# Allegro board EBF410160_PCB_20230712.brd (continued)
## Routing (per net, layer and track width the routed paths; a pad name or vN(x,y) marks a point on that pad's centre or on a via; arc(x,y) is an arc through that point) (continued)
MIPI_CSI_RX_CLK0N: length 108.7
  TOP w0.124: v1(43.21,59.12) 43.06,58.96 43.06,58.63 43.13,58.56 J5.78
  ART03 w0.113: v1(43.21,59.12) 43.04,58.95 43.04,58.53 43.15,58.42 43.8,58.42 44.5,59.12 45.79,59.12 46.48,58.42 46.74,58.42 47.29,58.97 47.29,59.13 46.75,59.67 46.75,60.09 47.1,60.43 47.52,60.43 48.05,59.9 48.21,59.9 50.16,61.85 67.95,61.85 69.28,63.18 78.3,63.18 78.99,62.48 84.84,62.48 85.6,63.24 87.76,63.24 88.58,64.07 92.9,64.07 94.11,65.28 124.79,65.28 126.49,66.98 126.49,68.07 127.51,69.09 128.27,69.09 129.2,70.02 arc(129.25,70.14) 129.2,70.27 arc(129.17,70.35) 129.2,70.43 129.36,70.59 arc(129.44,70.62) 129.52,70.59 arc(129.64,70.54) 129.77,70.59 129.84,70.65 arc(129.89,70.78) 129.84,70.91 arc(129.78,71.03) 129.84,71.16 129.9,71.23 arc(130.03,71.28) 130.16,71.23 arc(130.28,71.17) 130.41,71.23 131.25,72.06 132.21,72.06 132.39,71.88 133.54,71.88 133.72,72.06 134.57,72.06 v1(134.75,72.24)
  BOTTOM w0.124: v1(134.75,72.24) 134.58,72.07 131.37,72.07 131.28,72.16 J23.10
MIPI_CSI_RX_CLK0P: length 108.5
  TOP w0.124: v1(42.55,59.12) 42.73,58.94 42.73,58.64 42.63,58.54 J5.76
  ART03 w0.113: v1(42.55,59.12) 42.72,58.95 42.72,58.4 43.02,58.1 43.93,58.1 44.63,58.8 45.65,58.8 46.35,58.1 46.87,58.1 47.6,58.84 47.6,59.26 47.07,59.8 47.07,59.96 47.23,60.12 47.39,60.12 47.92,59.58 48.34,59.58 50.3,61.53 68.08,61.53 69.41,62.86 78.17,62.86 78.86,62.17 84.97,62.17 85.73,62.93 87.89,62.93 88.71,63.75 93.03,63.75 94.24,64.96 124.92,64.96 126.81,66.85 126.81,67.94 127.64,68.77 128.4,68.77 131.38,71.75 132.08,71.75 132.26,71.57 133.67,71.57 133.85,71.75 134.57,71.75 v1(134.75,71.57)
  BOTTOM w0.124: v1(134.75,71.57) 134.58,71.74 131.37,71.74 131.28,71.66 J23.9
MIPI_CSI_RX_CLK1N: length 133.5
  TOP w0.124: v1(44.7,52.83) 44.45,53.08 44.45,59.7 43.95,60.2 43.38,60.2 43.13,60.45 J5.77
  ART03 w0.113: v1(124.09,55.48) 123.98,55.37 123.52,55.37 123.41,55.48 123.41,56.34 123.11,56.64 122.62,56.64 122.32,56.34 122.32,55.1 122.21,54.99 121.92,54.99 121.81,55.1 121.81,56.34 121.51,56.64 121.02,56.64 120.73,56.34 120.73,55.1 120.61,54.99 120.39,54.99 120.27,55.1 120.27,56.34 119.98,56.64 119.49,56.64 119.19,56.34 119.19,55.12 119.06,54.99 118.82,54.99 118.71,55.1 118.71,55.71 118.41,56.01 117.92,56.01 117.62,55.71 117.62,55.1 117.51,54.99 112.58,54.99 107.06,49.46 103.63,49.46 102.93,48.77 78.74,48.77 76.96,50.54 76.34,50.54 76.05,50.25 76.05,48.81 75.93,48.7 75.71,48.7 75.6,48.81 75.6,50.25 75.3,50.54 74.81,50.54 74.51,50.25 74.51,48.81 74.4,48.7 74.17,48.7 74.06,48.81 74.06,50.25 73.76,50.54 73.26,50.54 72.96,50.25 72.96,49.07 72.85,48.96 72.63,48.96 72.51,49.07 72.51,50.25 72.21,50.54 66.04,50.54 64.77,49.27 59.2,49.27 59.08,49.39 59.08,50.88 58.79,51.18 58.3,51.18 58,50.88 58,49.18 57.72,48.89 57.02,48.89 56.27,49.65 56.27,49.81 57.38,50.91 57.38,51.33 57.03,51.68 56.61,51.68 55.51,50.57 55.35,50.57 55.19,50.73 55.19,50.89 56.21,51.92 56.21,52.34 55.87,52.68 55.45,52.68 54.42,51.66 54.26,51.66 53.72,52.2 50.54,52.2 arc(50.45,52.23) 50.41,52.32 arc(50.38,52.41) 50.29,52.45 50.09,52.45 arc(50,52.41) 49.96,52.32 arc(49.92,52.23) 49.84,52.2 49.64,52.2 arc(49.55,52.23) 49.51,52.32 arc(49.47,52.41) 49.38,52.45 49.19,52.45 arc(49.1,52.41) 49.06,52.32 arc(49.02,52.23) 48.93,52.2 48.36,52.2 48.25,52.31 48.25,52.79 47.95,53.08 47.46,53.08 47.16,52.79 47.16,52.5 47.05,52.38 46.82,52.38 46.71,52.5 46.71,52.79 46.41,53.08 45.93,53.08 45.63,52.79 45.63,52.31 45.52,52.2 44.7,52.2 44.51,52.38 44.51,52.64 v1(44.7,52.83)
  BOTTOM w0.124: J24.10 129.6,55.39 129.5,55.29 124.29,55.29 v1(124.09,55.48)
MIPI_CSI_RX_CLK1P: length 133.6
  TOP w0.124: J5.75 42.63,60.49 43.25,59.87 43.82,59.87 44.12,59.57 44.12,53.01 v1(43.94,52.83)
  ART03 w0.113: v1(43.94,52.83) 44.2,52.58 44.2,52.25 44.57,51.88 45.65,51.88 45.94,52.18 45.94,52.66 46.06,52.77 46.28,52.77 46.4,52.66 46.4,52.37 46.69,52.07 47.18,52.07 47.48,52.37 47.48,52.66 47.59,52.77 47.82,52.77 47.93,52.66 47.93,52.18 48.23,51.88 53.59,51.88 54.13,51.34 54.55,51.34 55.58,52.37 55.74,52.37 55.9,52.21 55.9,52.05 54.87,51.02 54.87,50.6 55.21,50.26 55.64,50.26 56.74,51.36 56.9,51.36 57.06,51.2 57.06,51.04 55.96,49.94 55.96,49.52 56.89,48.58 57.85,48.58 58.32,49.04 58.32,50.75 58.43,50.86 58.65,50.86 58.77,50.75 58.77,49.26 59.07,48.96 64.9,48.96 66.17,50.23 72.08,50.23 72.2,50.12 72.2,48.94 72.49,48.64 72.98,48.64 73.28,48.94 73.28,50.12 73.39,50.23 73.63,50.23 73.74,50.12 73.74,48.68 74.04,48.39 74.53,48.39 74.83,48.68 74.83,50.12 74.94,50.23 75.17,50.23 75.28,50.12 75.28,48.68 75.58,48.39 76.06,48.39 76.36,48.68 76.36,50.12 76.47,50.23 76.83,50.23 78.61,48.45 103.06,48.45 103.76,49.15 107.19,49.15 112.71,54.67 117.64,54.67 117.94,54.97 117.94,55.58 118.05,55.69 118.28,55.69 118.39,55.58 118.39,54.97 118.69,54.67 119.19,54.67 119.51,54.99 119.51,56.21 119.62,56.33 119.85,56.33 119.96,56.21 119.96,54.97 120.26,54.67 120.74,54.67 121.04,54.97 121.04,56.21 121.15,56.33 121.38,56.33 121.49,56.21 121.49,54.97 121.79,54.67 122.34,54.67 122.64,54.97 122.64,56.21 122.75,56.33 122.98,56.33 123.09,56.21 123.09,55.35 123.39,55.06 123.86,55.06 v1(124.09,54.82)
  BOTTOM w0.124: v1(124.09,54.82) 124.23,54.96 129.53,54.96 129.6,54.89 J24.9
MIPI_CSI_RX_D0N: length 108.4
  TOP w0.124: v1(41.21,59.12) 41.06,58.96 41.06,58.63 41.13,58.56 J5.70
  ART03 w0.113: v1(41.21,59.12) 40.94,59.39 40.94,59.93 41.41,60.39 42.54,60.39 43.05,59.88 45.22,59.88 45.61,60.27 arc(45.72,60.32) 45.83,60.27 arc(45.91,60.24) 45.99,60.27 46.15,60.43 arc(46.18,60.51) 46.15,60.59 arc(46.1,60.7) 46.15,60.81 46.25,60.91 arc(46.36,60.96) 46.47,60.91 arc(46.55,60.88) 46.63,60.91 46.79,61.07 arc(46.82,61.15) 46.79,61.23 arc(46.74,61.34) 46.79,61.45 46.88,61.55 arc(46.99,61.6) 47.11,61.55 arc(47.18,61.52) 47.26,61.55 47.42,61.71 arc(47.46,61.79) 47.42,61.87 arc(47.38,61.98) 47.42,62.09 47.63,62.29 67.69,62.29 69.03,63.63 78.74,63.63 78.93,63.44 79.4,63.44 arc(79.47,63.41) 79.5,63.34 arc(79.53,63.27) 79.59,63.24 79.85,63.24 arc(79.92,63.27) 79.95,63.34 arc(79.98,63.41) 80.05,63.44 84.29,63.44 84.68,63.82 87.38,63.82 88.65,65.09 92.71,65.09 93.42,65.79 108.77,65.79 109.07,66.09 109.07,66.25 109.18,66.36 109.41,66.36 109.52,66.25 109.52,66.09 109.82,65.79 110.31,65.79 110.6,66.09 110.6,66.25 110.72,66.36 110.94,66.36 111.06,66.25 111.06,66.09 111.35,65.79 112.23,65.79 112.67,66.23 113.3,66.23 113.74,65.79 123.14,65.79 131.19,73.85 131.75,73.85 arc(131.86,73.8) 131.91,73.69 arc(131.96,73.58) 132.07,73.53 132.2,73.53 arc(132.31,73.58) 132.36,73.69 arc(132.41,73.8) 132.52,73.85 133.35,73.85 133.48,73.72 133.48,73.18 133.36,73.06 133.16,73.06 v1(132.98,73.24)
  BOTTOM w0.124: v1(132.98,73.24) 132.82,73.07 131.37,73.07 131.28,73.16 J23.12
MIPI_CSI_RX_D0P: length 108.4
  TOP w0.124: J5.68 40.63,58.54 40.73,58.64 40.73,58.94 v1(40.55,59.12)
  ART03 w0.113: v1(40.55,59.12) 40.63,59.2 40.63,60.06 41.27,60.7 42.67,60.7 43.18,60.2 45.08,60.2 47.5,62.61 67.56,62.61 68.9,63.94 78.87,63.94 79.06,63.75 84.16,63.75 84.55,64.13 87.25,64.13 88.52,65.4 92.58,65.4 93.29,66.11 108.64,66.11 108.75,66.22 108.75,66.38 109.05,66.67 109.54,66.67 109.84,66.38 109.84,66.22 109.95,66.11 110.18,66.11 110.29,66.22 110.29,66.38 110.59,66.67 111.07,66.67 111.37,66.38 111.37,66.22 111.48,66.11 112.1,66.11 112.54,66.55 113.43,66.55 113.87,66.11 123.01,66.11 131.06,74.17 133.48,74.17 133.79,73.85 133.79,73.04 133.5,72.75 133.16,72.75 v1(132.98,72.57)
  BOTTOM w0.124: v1(132.98,72.57) 132.82,72.74 131.37,72.74 131.28,72.66 J23.11
MIPI_CSI_RX_D1N: length 108.6
  TOP w0.124: J5.74 42.13,56.69 42.03,56.6 42.03,56.3 v1(42.21,56.12)
  ART03 w0.113: v1(42.21,56.12) 42.05,56.27 42.05,56.85 42.29,57.09 47.25,57.09 50.87,60.7 68.39,60.7 69.79,62.1 77.66,62.1 79.12,60.64 80.27,60.64 80.9,61.28 82.05,61.28 82.49,60.84 83.26,60.84 83.87,61.45 85.97,61.45 86.55,62.04 88.9,62.04 89.2,62.34 89.2,62.69 89.31,62.8 89.53,62.8 89.65,62.69 89.65,62.34 89.94,62.04 90.43,62.04 90.73,62.34 90.73,62.69 90.84,62.8 91.07,62.8 91.18,62.69 91.18,62.34 91.48,62.04 92.97,62.04 94.62,63.69 116.08,63.69 116.64,64.25 125.91,64.25 131.45,69.79 132.58,69.79 132.78,69.59 133.7,69.59 134.11,70.01 134.11,70.36 v1(134.37,70.61)
  BOTTOM w0.124: J23.8 133.82,71.16 v1(134.37,70.61)
MIPI_CSI_RX_D1P: length 108.4
  TOP w0.124: J5.72 41.63,56.68 41.7,56.61 41.7,56.27 v1(41.55,56.12)
  ART03 w0.113: v1(41.55,56.12) 41.74,56.31 41.74,56.98 42.16,57.4 44.15,57.4 arc(44.24,57.44) 44.27,57.53 arc(44.31,57.62) 44.4,57.66 44.6,57.66 arc(44.69,57.62) 44.72,57.53 arc(44.76,57.44) 44.85,57.4 45.05,57.4 arc(45.14,57.44) 45.17,57.53 arc(45.21,57.62) 45.3,57.66 45.5,57.66 arc(45.59,57.62) 45.63,57.53 arc(45.66,57.44) 45.75,57.4 47.12,57.4 50.73,61.02 68.26,61.02 69.66,62.42 77.79,62.42 79.25,60.96 80.14,60.96 80.77,61.59 82.18,61.59 82.62,61.16 83.13,61.16 83.74,61.77 85.83,61.77 86.42,62.36 88.77,62.36 88.88,62.47 88.88,62.82 89.18,63.12 89.66,63.12 89.96,62.82 89.96,62.47 90.08,62.36 90.3,62.36 90.41,62.47 90.41,62.82 90.71,63.12 91.2,63.12 91.5,62.82 91.5,62.47 91.61,62.36 92.84,62.36 94.49,64.01 115.95,64.01 116.51,64.56 125.78,64.56 131.32,70.1 132.72,70.1 132.91,69.91 133.57,69.91 133.8,70.14 133.8,70.42 v1(133.6,70.61)
  BOTTOM w0.124: J23.7 131.36,70.66 131.53,70.83 133.48,70.83 133.6,70.7 v1(133.6,70.61)
MIPI_CSI_RX_D2N: length 94.9
  TOP w0.124: J5.69 41.13,62.76 41.02,62.86 41.02,64.27 41.4,64.65 41.4,65.25 41.09,65.57 40.73,65.57 v1(40.51,65.78)
  ART03 w0.113: v1(40.51,65.78) 40.64,65.66 40.83,65.66 43.11,67.94 55.5,67.94 56.45,66.99 65.15,66.99 66.94,68.78 85.24,68.78 87.87,71.41 107.7,71.41 108.5,72.21 119.07,72.21 121.92,75.06 123.19,75.06 124.21,76.07 124.84,76.07 124.97,76.2 v1(124.97,76.45)
MIPI_CSI_RX_D2P: length 95.3
  TOP w0.124: J5.67 40.63,62.85 40.69,62.92 40.69,64.41 41.07,64.79 41.07,65.12 40.95,65.24 40.73,65.24 v1(40.51,65.02)
  ART03 w0.113: v1(40.51,65.02) 40.51,65.06 40.73,65.28 40.89,65.28 41.07,65.46 arc(41.16,65.5) 41.25,65.46 arc(41.34,65.42) 41.44,65.46 41.57,65.6 arc(41.61,65.69) 41.57,65.78 arc(41.54,65.87) 41.57,65.96 41.71,66.1 arc(41.8,66.13) 41.89,66.1 arc(41.98,66.06) 42.07,66.1 42.21,66.24 arc(42.25,66.33) 42.21,66.42 arc(42.17,66.51) 42.21,66.6 43.24,67.63 44.57,67.63 arc(44.64,67.6) 44.67,67.53 arc(44.7,67.46) 44.76,67.44 45.02,67.44 arc(45.09,67.46) 45.12,67.53 arc(45.15,67.6) 45.22,67.63 45.48,67.63 arc(45.54,67.6) 45.57,67.53 arc(45.6,67.46) 45.67,67.44 45.93,67.44 arc(45.99,67.46) 46.02,67.53 arc(46.05,67.6) 46.12,67.63 55.37,67.63 56.32,66.67 65.28,66.67 67.07,68.47 85.37,68.47 88,71.09 107.83,71.09 108.63,71.89 119.2,71.89 122.05,74.74 123.32,74.74 124.34,75.76 124.78,75.76 124.97,75.56 v1(124.97,75.44)
MIPI_CSI_RX_D3N: length 95.7
  TOP w0.124: v1(42.29,64.01) 42.06,63.77 42.06,62.92 42.13,62.84 J5.73
  ART03 w0.113: v1(124.97,78.48) 124.97,78.34 125.15,78.17 125.54,78.17 126.11,77.6 126.11,75.44 125.16,74.49 124.21,74.49 120.83,71.11 109.19,71.11 108.4,70.32 88.34,70.32 85.65,67.63 67.44,67.63 65.72,65.91 54.93,65.91 54.43,66.41 44.12,66.41 42.1,64.39 42.1,64.2 v1(42.29,64.01)
MIPI_CSI_RX_D3P: length 95.7
  TOP w0.124: J5.71 41.63,62.82 41.73,62.92 41.73,63.81 v1(41.53,64.01)
  ART03 w0.113: v1(124.97,77.47) 124.97,77.72 125.09,77.85 125.41,77.85 125.8,77.47 125.8,75.57 125.03,74.8 124.08,74.8 120.7,71.43 109.06,71.43 108.27,70.63 88.21,70.63 85.52,67.94 67.31,67.94 65.59,66.23 55.06,66.23 54.56,66.72 43.99,66.72 42.6,65.34 arc(42.48,65.29) 42.35,65.34 arc(42.23,65.39) 42.1,65.34 42.03,65.27 arc(41.98,65.15) 42.03,65.02 arc(42.09,64.9) 42.03,64.77 41.78,64.52 41.78,64.26 v1(41.53,64.01)
MIPI_DSI_TX0_CLKN: length 114.1
  TOP w0.124: v1(133.56,75.83) 133.37,75.64 133.37,75.64 133.27,75.54 130.91,75.54 130.82,75.62 J21.24 ; v1(37.21,64.01) 37.06,63.85 37.06,62.92 37.13,62.84 J5.53
  ART03 w0.113: v1(37.21,64.01) 37.08,63.88 37.08,63.48 37.24,63.32 42.5,63.32 44.93,65.75 53.56,65.75 53.85,65.47 67.12,65.47 68.83,67.18 79.88,67.18 80.55,66.52 82.77,66.52 83.44,67.18 85.93,67.18 88.04,69.29 109.05,69.29 110.29,70.54 122.99,70.54 125.48,73.02 125.48,74.04 128.65,77.21 130.05,77.21 130.54,76.72 130.54,75.23 130.65,75.12 130.88,75.12 130.99,75.23 130.99,76.24 131.29,76.54 131.78,76.54 132.07,76.24 132.07,75.8 132.19,75.68 133.42,75.68 v1(133.56,75.83)
MIPI_DSI_TX0_CLKP: length 115.4
  TOP w0.124: v1(133.56,75.17) 133.52,75.21 130.99,75.21 130.91,75.12 J21.23 ; J5.51 36.63,62.82 36.73,62.92 36.73,63.83 v1(36.55,64.01)
  ART03 w0.113: v1(133.56,75.17) 133.37,75.37 133.02,75.37 arc(132.92,75.33) 132.88,75.23 arc(132.84,75.14) 132.75,75.1 132.57,75.1 arc(132.47,75.14) 132.43,75.23 arc(132.39,75.33) 132.3,75.37 132.06,75.37 131.76,75.66 131.76,76.11 131.65,76.22 131.42,76.22 131.31,76.11 131.31,75.1 131.01,74.8 130.52,74.8 130.22,75.1 130.22,76.59 129.92,76.9 128.78,76.9 128.19,76.31 arc(128.16,76.23) 128.19,76.14 arc(128.23,76.06) 128.19,75.97 128.04,75.82 arc(127.96,75.79) 127.88,75.82 arc(127.79,75.86) 127.71,75.82 127.56,75.67 arc(127.52,75.59) 127.56,75.5 arc(127.59,75.42) 127.56,75.34 127.41,75.19 arc(127.32,75.15) 127.24,75.19 arc(127.15,75.22) 127.07,75.19 125.79,73.91 125.79,72.89 123.12,70.23 110.42,70.23 109.18,68.98 88.17,68.98 86.06,66.87 83.57,66.87 82.9,66.2 80.42,66.2 79.75,66.87 68.96,66.87 67.25,65.15 53.72,65.15 53.43,65.44 45.06,65.44 42.63,63.01 37.11,63.01 36.77,63.35 36.77,63.79 v1(36.55,64.01)
MIPI_DSI_TX0_D0N: length 115
  TOP w0.124: J21.27 130.82,77.12 130.99,76.96 131.51,76.96 v1(131.64,77.09) ; J5.43 34.63,62.84 34.56,62.92 34.56,65.21 36.4,67.05 v1(36.96,67.05)
  ART03 w0.113: v1(36.96,67.05) 36.91,67.1 36.91,67.58 37.08,67.75 arc(37.15,67.78) 37.23,67.75 arc(37.3,67.72) 37.37,67.75 37.55,67.92 arc(37.58,67.99) 37.55,68.07 arc(37.52,68.14) 37.55,68.21 37.72,68.39 arc(37.79,68.42) 37.87,68.39 arc(37.94,68.36) 38.01,68.39 38.19,68.56 arc(38.22,68.63) 38.19,68.71 arc(38.15,68.78) 38.19,68.85 38.36,69.02 arc(38.43,69.05) 38.5,69.02 arc(38.58,68.99) 38.65,69.02 38.82,69.2 arc(38.85,69.27) 38.82,69.34 arc(38.79,69.42) 38.82,69.49 39.01,69.67 55.99,69.67 56.17,69.49 57.53,68.13 63.85,68.13 65.71,69.99 84.01,69.99 87.23,73.21 107,73.21 108.06,74.27 116.61,74.27 117.66,75.33 117.66,75.88 122.3,80.52 130.56,80.52 132.07,79.01 132.07,78.73 arc(132.03,78.63) 131.93,78.58 arc(131.82,78.54) 131.78,78.44 131.78,78.28 arc(131.82,78.17) 131.93,78.13 arc(132.03,78.09) 132.07,77.99 132.07,77.52 v1(131.64,77.09)
MIPI_DSI_TX0_D0P: length 115.3
  TOP w0.124: v1(36.45,67.56) 34.23,65.34 34.23,62.92 34.13,62.82 J5.41 ; v1(132.38,77.1) 131.91,76.62 J21.26
  ART03 w0.113: v1(132.38,77.1) 132.38,79.14 130.69,80.83 122.17,80.83 117.35,76.01 117.35,75.46 116.48,74.59 107.92,74.59 106.87,73.53 87.1,73.53 83.88,70.31 65.58,70.31 63.72,68.45 57.66,68.45 56.49,69.62 56.12,69.99 38.88,69.99 v1(36.45,67.56)
MIPI_DSI_TX0_D1N: length 115.8
  TOP w0.124: v1(127.64,74.17) 127.82,73.98 128.92,73.98 129.06,74.12 J21.21 ; J5.47 35.63,62.79 35.51,62.92 35.51,63.83 v1(35.69,64.01)
  ART03 w0.113: v1(35.69,64.01) 35.49,63.81 35.49,62.72 35.61,62.61 36.45,62.61 36.89,62.17 36.89,61.13 37,61.02 37.23,61.02 37.34,61.13 37.34,61.99 37.83,62.48 42.87,62.48 45.35,64.96 53.27,64.96 53.56,64.68 65.5,64.68 65.96,64.21 67.01,64.21 68.29,65.49 74.57,65.49 75.43,66.35 76.27,66.35 77.13,65.49 77.94,65.49 78.25,65.8 85.68,65.8 88.32,68.45 92.83,68.45 93.13,68.15 93.13,67.88 93.24,67.77 93.47,67.77 93.58,67.88 93.58,68.15 93.88,68.45 94.37,68.45 94.67,68.15 94.67,67.88 94.78,67.77 95,67.77 95.12,67.88 95.12,68.15 95.41,68.45 95.9,68.45 96.2,68.15 96.2,67.88 96.31,67.77 96.54,67.77 96.65,67.88 96.65,68.15 96.95,68.45 97.44,68.45 97.73,68.15 97.73,67.88 97.85,67.77 98.07,67.77 98.19,67.88 98.19,68.15 98.48,68.45 99.88,68.45 100.18,68.15 100.18,67.86 100.29,67.75 100.52,67.75 100.63,67.86 100.63,68.15 100.93,68.45 101.42,68.45 101.71,68.15 101.71,67.86 101.83,67.75 102.05,67.75 102.17,67.86 102.17,68.15 102.46,68.45 102.95,68.45 103.25,68.15 103.25,67.86 103.36,67.75 103.59,67.75 103.7,67.86 103.7,68.15 104,68.45 104.48,68.45 104.78,68.15 104.78,67.86 104.9,67.75 105.12,67.75 105.23,67.86 105.23,68.15 105.53,68.45 106.03,68.45 106.33,68.15 106.33,67.86 106.44,67.75 106.67,67.75 106.78,67.86 106.78,68.15 107.08,68.45 112.21,68.45 113.48,69.72 123.92,69.72 126.62,72.42 126.62,73.62 127.04,74.04 127.5,74.04 v1(127.64,74.17)
MIPI_DSI_TX0_D1P: length 116.3
  TOP w0.124: J5.45 35.13,62.81 35.18,62.86 35.18,63.85 v1(35.03,64.01) ; v1(127.64,73.51) 127.75,73.62 J21.20
  ART03 w0.113: v1(127.64,73.51) 127.42,73.72 127.17,73.72 126.93,73.49 126.93,72.29 124.05,69.4 113.61,69.4 112.34,68.13 107.21,68.13 107.1,68.02 107.1,67.73 106.8,67.44 106.31,67.44 106.02,67.73 106.02,68.02 105.9,68.13 105.66,68.13 105.55,68.02 105.55,67.73 105.25,67.44 104.76,67.44 104.47,67.73 104.47,68.02 104.35,68.13 104.13,68.13 104.02,68.02 104.02,67.73 103.72,67.44 103.23,67.44 102.93,67.73 102.93,68.02 102.82,68.13 102.59,68.13 102.48,68.02 102.48,67.73 102.18,67.44 101.7,67.44 101.4,67.73 101.4,68.02 101.29,68.13 101.06,68.13 100.95,68.02 100.95,67.73 100.65,67.44 100.16,67.44 99.86,67.73 99.86,68.02 99.75,68.13 98.61,68.13 98.5,68.02 98.5,67.75 98.2,67.45 97.72,67.45 97.42,67.75 97.42,68.02 97.31,68.13 97.08,68.13 96.97,68.02 96.97,67.75 96.67,67.45 96.18,67.45 95.88,67.75 95.88,68.02 95.77,68.13 95.55,68.13 95.43,68.02 95.43,67.75 95.14,67.45 94.65,67.45 94.35,67.75 94.35,68.02 94.24,68.13 94.01,68.13 93.9,68.02 93.9,67.75 93.6,67.45 93.11,67.45 92.82,67.75 92.82,68.02 92.7,68.13 88.45,68.13 85.81,65.49 78.38,65.49 78.07,65.18 77,65.18 76.13,66.04 75.56,66.04 74.7,65.18 68.42,65.18 67.14,63.9 65.83,63.9 65.36,64.36 53.43,64.36 53.14,64.65 45.48,64.65 43,62.17 37.96,62.17 37.65,61.86 37.65,61 37.36,60.7 36.87,60.7 36.57,61 36.57,62.04 36.32,62.29 35.48,62.29 35.18,62.59 35.18,63.85 v1(35.03,64.01)
MIPI_DSI_TX0_D2N: length 114.9
  TOP w0.124: J21.18 129.27,72.62 129.09,72.45 128.46,72.45 v1(128.27,72.64) ; v1(38.73,60.07) 38.53,60.27 38.53,60.5 38.63,60.6 J5.59
  ART03 w0.113: v1(128.27,72.64) 128.24,72.64 128.02,72.41 128.02,71.94 124.59,68.52 123.81,68.52 arc(123.69,68.47) 123.65,68.36 arc(123.6,68.24) 123.49,68.2 123.36,68.2 arc(123.24,68.24) 123.2,68.36 arc(123.15,68.47) 123.04,68.52 122.47,68.52 122.36,68.4 122.36,66.97 122.06,66.67 121.58,66.67 121.28,66.97 121.28,68.4 121.17,68.52 120.94,68.52 120.83,68.4 120.83,66.97 120.53,66.67 120.04,66.67 119.74,66.97 119.74,68.4 119.63,68.52 119.41,68.52 119.29,68.4 119.29,66.97 119,66.67 118.51,66.67 118.21,66.97 118.21,68.4 118.1,68.52 115.58,68.52 115.47,68.4 115.47,66.97 115.17,66.67 114.69,66.67 114.39,66.97 114.39,68.4 114.28,68.52 113.92,68.52 112.65,67.25 107.89,67.25 107.25,66.61 92.97,66.61 92.33,65.98 89.62,65.98 89.33,66.27 89.33,67.26 89.21,67.37 88.99,67.37 88.87,67.26 88.87,66.27 88.58,65.98 88.14,65.98 86.84,64.67 78.96,64.67 78.7,64.4 68.79,64.4 67.44,63.06 45.09,63.06 43.31,61.28 41.02,61.28 40.71,60.96 39.9,60.96 39.58,61.28 39.12,61.28 38.61,60.77 38.61,60.2 v1(38.73,60.07)
MIPI_DSI_TX0_D2P: length 115.3
  TOP w0.124: v1(127.51,72.64) 128.03,72.12 J21.17 ; v1(38.07,60.07) 38.08,60.07 38.2,60.19 38.2,60.6 38.13,60.68 J5.57
  ART03 w0.113: v1(127.51,72.64) 127.7,72.45 127.7,72.07 124.46,68.83 122.34,68.83 122.05,68.54 122.05,67.1 121.93,66.99 121.71,66.99 121.59,67.1 121.59,68.54 121.3,68.83 120.81,68.83 120.51,68.54 120.51,67.1 120.4,66.99 120.17,66.99 120.06,67.1 120.06,68.54 119.76,68.83 119.28,68.83 118.98,68.54 118.98,67.1 118.86,66.99 118.64,66.99 118.53,67.1 118.53,68.54 118.23,68.83 115.45,68.83 115.15,68.54 115.15,67.1 115.04,66.99 114.82,66.99 114.7,67.1 114.7,68.54 114.41,68.83 113.79,68.83 112.52,67.56 107.76,67.56 107.12,66.93 92.84,66.93 92.2,66.29 89.75,66.29 89.64,66.41 89.64,67.39 89.34,67.69 88.86,67.69 88.56,67.39 88.56,66.41 88.45,66.29 88.01,66.29 86.71,64.99 78.83,64.99 78.56,64.72 68.66,64.72 67.31,63.37 44.96,63.37 43.18,61.59 40.89,61.59 40.57,61.27 40.03,61.27 39.71,61.59 38.99,61.59 38.29,60.9 38.29,60.28 38.08,60.07 v1(38.07,60.07)
MIPI_DSI_TX0_D3N: length 115.2
  TOP w0.124: v1(128.17,78.7) 128.43,78.45 128.97,78.45 129.14,78.62 J21.30 ; v1(39.75,64.01) 39.52,63.77 39.52,62.97 39.63,62.86 J5.63
  ART03 w0.113: v1(39.75,64.01) 39.55,64.21 39.55,66.41 arc(39.6,66.53) 39.72,66.58 arc(39.82,66.62) 39.86,66.72 39.86,66.88 arc(39.82,66.98) 39.72,67.03 arc(39.6,67.08) 39.55,67.19 39.55,67.31 arc(39.6,67.43) 39.72,67.48 arc(39.82,67.52) 39.86,67.63 39.86,67.78 arc(39.82,67.89) 39.72,67.93 arc(39.6,67.98) 39.55,68.1 39.55,68.48 39.97,68.9 40.48,68.9 40.59,68.79 40.59,68.11 40.89,67.82 41.38,67.82 41.67,68.11 41.67,68.79 41.79,68.9 42.77,68.9 arc(42.83,68.87) 42.86,68.8 arc(42.89,68.73) 42.96,68.71 43.22,68.71 arc(43.29,68.73) 43.31,68.8 arc(43.34,68.87) 43.41,68.9 55.37,68.9 56.88,67.39 64.85,67.39 66.74,69.28 84.96,69.28 87.56,71.88 106.87,71.88 108.34,73.35 119.32,73.35 120.9,74.93 120.9,76.61 120.49,77.02 120.49,77.18 120.65,77.33 120.81,77.33 121.15,76.99 121.57,76.99 121.92,77.34 121.92,77.76 121.58,78.1 121.58,78.26 123.01,79.69 125.4,79.69 arc(125.47,79.66) 125.49,79.6 arc(125.52,79.53) 125.59,79.5 125.85,79.5 arc(125.92,79.53) 125.94,79.6 arc(125.97,79.66) 126.04,79.69 126.3,79.69 arc(126.37,79.66) 126.4,79.6 arc(126.42,79.53) 126.49,79.5 126.75,79.5 arc(126.82,79.53) 126.85,79.6 arc(126.87,79.66) 126.94,79.69 127.2,79.69 arc(127.27,79.66) 127.3,79.6 arc(127.33,79.53) 127.39,79.5 127.65,79.5 arc(127.72,79.53) 127.75,79.6 arc(127.78,79.66) 127.84,79.69 128.1,79.69 arc(128.17,79.66) 128.2,79.6 arc(128.23,79.53) 128.3,79.5 128.56,79.5 arc(128.62,79.53) 128.65,79.6 arc(128.68,79.66) 128.75,79.69 129.46,79.69 130,79.15 130,78.64 129.72,78.36 129.41,78.36 arc(129.34,78.39) 129.31,78.46 arc(129.26,78.58) 129.15,78.62 129.02,78.62 arc(128.91,78.58) 128.86,78.46 arc(128.83,78.39) 128.76,78.36 128.52,78.36 v1(128.17,78.7)
MIPI_DSI_TX0_D3P: length 114.3
  TOP w0.124: v1(39.09,64.01) 39.19,63.91 39.19,62.94 39.13,62.88 J5.61 ; J21.29 128.25,78.12 v1(128.17,78.04)
  ART03 w0.113: v1(128.17,78.04) 129.85,78.04 130.32,78.51 130.32,79.28 129.59,80.01 122.88,80.01 121.26,78.39 121.26,77.97 121.6,77.63 121.6,77.47 121.44,77.31 121.28,77.31 120.94,77.65 120.52,77.65 120.18,77.31 120.18,76.89 120.59,76.47 120.59,75.06 119.19,73.66 108.21,73.66 106.74,72.19 87.43,72.19 84.83,69.59 66.61,69.59 64.72,67.7 57.01,67.7 55.5,69.21 41.66,69.21 41.36,68.92 41.36,68.25 41.25,68.13 41.02,68.13 40.91,68.25 40.91,68.92 40.61,69.21 39.83,69.21 39.23,68.61 39.23,64.15 v1(39.09,64.01)
MIPI_DSI_TX1_CLKN: length 128.1
  TOP w0.124: v1(128.75,53.47) 128.78,53.44 129.9,53.44 J22.24 ; J5.27 30.63,62.59 30.55,62.66 30.55,63.98 v1(30.71,64.14)
  ART03 w0.113: v1(128.75,53.47) 128.57,53.29 128.04,53.29 126.82,52.07 122.43,52.07 122.05,51.69 122.05,51.48 121.94,51.37 121.71,51.37 121.6,51.48 121.6,52.15 121.3,52.45 120.81,52.45 120.51,52.15 120.51,51.48 120.4,51.37 120.18,51.37 120.06,51.48 120.06,52.15 119.76,52.45 119.28,52.45 118.98,52.15 118.98,51.48 118.87,51.37 118.64,51.37 118.53,51.48 118.53,52.15 118.23,52.45 117.7,52.45 117.35,52.1 117.35,51.56 117.22,51.43 113.66,51.43 108.33,46.1 56.07,46.1 52.64,49.53 36.96,49.53 36.07,50.42 arc(36.03,50.52) 36.07,50.61 arc(36.11,50.71) 36.07,50.8 35.94,50.93 arc(35.84,50.97) 35.75,50.93 arc(35.65,50.89) 35.56,50.93 35.43,51.06 arc(35.39,51.15) 35.43,51.25 arc(35.47,51.34) 35.43,51.44 35.3,51.57 arc(35.2,51.61) 35.11,51.57 arc(35.01,51.53) 34.92,51.57 34.42,52.07 31.88,52.07 30.54,53.41 30.54,54.95 30.65,55.06 30.94,55.06 31.24,55.36 31.24,55.85 30.94,56.14 30.65,56.14 30.54,56.26 30.54,56.48 30.65,56.59 31.2,56.59 31.5,56.89 31.5,57.38 31.2,57.68 30.65,57.68 30.54,57.79 30.54,61.42 30.24,61.72 29.89,61.72 29.78,61.83 29.78,62.19 29.89,62.3 30.24,62.3 30.54,62.6 30.54,63.96 v1(30.71,64.14)
MIPI_DSI_TX1_CLKP: length 128.1
  TOP w0.124: v1(30.05,64.14) 30.23,63.96 30.23,62.66 30.13,62.56 J5.25 ; v1(128.75,52.81) 128.75,52.81 129.06,53.11 129.9,53.11 J22.23
  ART03 w0.113: v1(128.75,52.81) 128.59,52.97 128.17,52.97 126.95,51.75 122.56,51.75 122.36,51.56 122.36,51.35 122.07,51.05 121.58,51.05 121.28,51.35 121.28,52.02 121.17,52.13 120.94,52.13 120.83,52.02 120.83,51.35 120.53,51.05 120.04,51.05 119.75,51.35 119.75,52.02 119.63,52.13 119.41,52.13 119.3,52.02 119.3,51.35 119,51.05 118.51,51.05 118.21,51.35 118.21,52.02 118.1,52.13 117.83,52.13 117.66,51.97 117.66,51.43 117.35,51.12 113.8,51.12 108.46,45.78 55.94,45.78 52.51,49.21 36.83,49.21 34.29,51.75 31.75,51.75 30.22,53.28 30.22,55.08 30.52,55.38 30.81,55.38 30.93,55.49 30.93,55.71 30.81,55.83 30.52,55.83 30.22,56.13 30.22,56.61 30.52,56.91 31.07,56.91 31.18,57.02 31.18,57.25 31.07,57.36 30.52,57.36 30.22,57.66 30.22,61.29 30.11,61.4 29.76,61.4 29.46,61.7 29.46,62.32 29.76,62.61 30.11,62.61 30.22,62.73 30.22,63.96 v1(30.05,64.14)
MIPI_DSI_TX1_D0N: length 127.5
  TOP w0.124: J5.17 28.13,60.51 28.06,60.44 28.06,59.44 v1(28.19,59.31) ; v1(133.35,55.12) 133.35,55.06 133.23,54.94 130.91,54.94 130.82,55.03 J22.27
  ART03 w0.113: v1(28.19,59.31) 28.04,59.15 28.04,53.62 31.37,50.29 33.09,50.29 33.4,49.98 arc(33.48,49.95) 33.55,49.98 arc(33.63,50.01) 33.71,49.98 33.87,49.82 arc(33.91,49.74) 33.87,49.66 arc(33.84,49.58) 33.87,49.5 34.03,49.34 arc(34.11,49.31) 34.19,49.34 arc(34.27,49.38) 34.35,49.34 34.51,49.18 arc(34.54,49.1) 34.51,49.02 arc(34.48,48.94) 34.51,48.87 35.5,47.88 52.14,47.88 55.44,44.58 110.11,44.58 114.17,48.64 125.98,48.64 127.89,50.54 131.83,50.54 132.59,51.31 132.59,54.58 132.89,54.88 133.11,54.88 v1(133.35,55.12)
MIPI_DSI_TX1_D0P: length 127.6
  TOP w0.124: v1(27.43,59.31) 27.73,59.61 27.73,60.41 27.63,60.51 J5.15 ; v1(133.35,54.46) 133.2,54.61 130.91,54.61 130.82,54.53 J22.26
  ART03 w0.113: v1(27.43,59.31) 27.72,59.02 27.72,53.49 31.24,49.98 32.95,49.98 35.37,47.56 52,47.56 55.31,44.26 110.24,44.26 114.3,48.32 126.11,48.32 128.02,50.23 131.96,50.23 132.9,51.18 132.9,54.45 133.02,54.56 133.25,54.56 v1(133.35,54.46)
MIPI_DSI_TX1_D1N: length 128.6
  TOP w0.124: v1(29.19,60.07) 29.03,60.22 29.03,60.6 29.13,60.7 J5.21 ; v1(131.95,52.2) 131.7,51.94 130.91,51.94 130.82,52.03 J22.21
  ART03 w0.113: v1(29.19,60.07) 28.99,59.88 28.99,58.61 29.11,58.49 29.42,58.49 29.72,58.2 29.72,57.71 29.42,57.41 28.98,57.41 28.87,57.3 28.87,57.07 28.98,56.96 29.42,56.96 29.72,56.66 29.72,56.18 29.42,55.88 28.98,55.88 28.87,55.76 28.87,55.54 28.98,55.43 29.42,55.43 29.72,55.13 29.72,54.64 29.42,54.34 28.98,54.34 28.87,54.23 28.87,53.94 31.62,51.18 33.72,51.18 34.18,50.72 arc(34.26,50.68) 34.34,50.72 arc(34.42,50.75) 34.5,50.72 34.66,50.56 arc(34.69,50.48) 34.66,50.4 arc(34.63,50.32) 34.66,50.24 34.82,50.08 arc(34.9,50.05) 34.98,50.08 arc(35.06,50.11) 35.14,50.08 35.3,49.92 arc(35.33,49.84) 35.3,49.76 arc(35.27,49.68) 35.3,49.6 36.13,48.77 52.32,48.77 55.75,45.34 108.97,45.34 114.06,50.43 119.72,50.43 120.02,50.14 120.02,49.7 120.14,49.59 120.36,49.59 120.47,49.7 120.47,50.14 120.77,50.43 121.26,50.43 121.56,50.14 121.56,49.7 121.67,49.59 121.9,49.59 122.01,49.7 122.01,50.14 122.31,50.43 122.79,50.43 123.09,50.14 123.09,49.7 123.2,49.59 123.43,49.59 123.54,49.7 123.54,50.14 123.84,50.43 124.33,50.43 124.63,50.14 124.63,49.7 124.74,49.59 124.96,49.59 125.08,49.7 125.08,50.14 125.74,50.8 126.87,50.8 127.53,51.46 129.06,51.46 129.86,52.26 130.81,52.26 131.07,52 131.76,52 v1(131.95,52.2)
MIPI_DSI_TX1_D1P: length 128.5
  TOP w0.124: v1(131.95,51.43) 131.78,51.61 130.91,51.61 130.82,51.53 J22.20 ; J5.19 28.63,60.68 28.71,60.6 28.71,60.25 v1(28.53,60.07)
  ART03 w0.113: v1(131.95,51.43) 131.7,51.69 130.94,51.69 130.68,51.94 129.99,51.94 129.19,51.14 127.66,51.14 127,50.48 125.87,50.48 125.39,50.01 125.39,49.57 125.09,49.27 124.61,49.27 124.31,49.57 124.31,50.01 124.2,50.12 123.97,50.12 123.86,50.01 123.86,49.57 123.56,49.27 123.07,49.27 122.78,49.57 122.78,50.01 122.66,50.12 122.44,50.12 122.32,50.01 122.32,49.57 122.03,49.27 121.54,49.27 121.24,49.57 121.24,50.01 121.13,50.12 120.9,50.12 120.79,50.01 120.79,49.57 120.49,49.27 120,49.27 119.71,49.57 119.71,50.01 119.59,50.12 114.19,50.12 109.1,45.02 55.62,45.02 52.19,48.45 36,48.45 33.59,50.86 31.49,50.86 28.55,53.81 28.55,54.36 28.85,54.66 29.29,54.66 29.4,54.77 29.4,55 29.29,55.11 28.85,55.11 28.55,55.41 28.55,55.9 28.85,56.19 29.29,56.19 29.4,56.31 29.4,56.53 29.29,56.64 28.85,56.64 28.55,56.94 28.55,57.43 28.85,57.73 29.29,57.73 29.4,57.84 29.4,58.07 29.29,58.18 28.97,58.18 28.68,58.48 28.68,59.92 v1(28.53,60.07)
MIPI_DSI_TX1_D2N: length 128.2
  TOP w0.124: J5.33 32.13,62.84 32.06,62.92 32.06,63.17 v1(32.21,63.32) ; J22.18 129.27,50.53 129.23,50.49 128.96,50.49 127.71,51.74 127.71,52.73 127.1,53.33 126.5,53.33 v1(126.36,53.47)
  ART03 w0.113: v1(126.36,53.47) 126.36,53.45 126.23,53.32 117.2,53.32 116.2,52.32 113.03,52.32 107.7,46.99 72.14,46.99 70.42,48.7 69.88,48.7 69.58,48.4 69.58,47.42 69.47,47.3 69.24,47.3 69.13,47.42 69.13,48.4 68.83,48.7 67.12,48.7 65.53,47.12 56.2,47.12 52.77,50.54 37.66,50.54 37.37,50.83 arc(37.34,50.91) 37.37,50.99 arc(37.41,51.06) 37.37,51.14 37.21,51.3 arc(37.13,51.34) 37.06,51.3 arc(36.98,51.27) 36.9,51.3 36.74,51.47 arc(36.7,51.54) 36.74,51.62 arc(36.77,51.7) 36.74,51.78 36.58,51.94 arc(36.5,51.98) 36.42,51.94 arc(36.34,51.91) 36.26,51.94 36.1,52.1 arc(36.07,52.18) 36.1,52.26 arc(36.13,52.34) 36.1,52.42 35.94,52.58 arc(35.86,52.61) 35.78,52.58 arc(35.7,52.55) 35.62,52.58 35.24,52.96 32.62,52.96 32.51,53.07 32.51,53.5 32.62,53.61 33.99,53.61 34.29,53.91 34.29,54.4 33.99,54.69 32.62,54.69 32.51,54.81 32.51,55.24 32.64,55.37 33.23,55.37 33.52,55.67 33.52,56.52 31.5,58.55 31.5,60.68 31.61,60.79 32.6,60.79 32.89,61.09 32.89,61.58 32.6,61.88 31.61,61.88 31.5,61.99 31.5,62.23 32,62.74 32,63.12 v1(32.21,63.32)
MIPI_DSI_TX1_D2P: length 128.1
  TOP w0.124: J22.17 129.16,50.02 129.03,50.16 128.83,50.16 127.38,51.61 127.38,52.59 126.97,53.01 126.57,53.01 v1(126.36,52.81) ; v1(31.55,63.32) 31.73,63.14 31.73,62.92 31.63,62.82 J5.31
  ART03 w0.113: v1(31.55,63.32) 31.69,63.18 31.69,62.87 31.18,62.36 31.18,61.86 31.48,61.56 32.46,61.56 32.58,61.45 32.58,61.22 32.46,61.11 31.48,61.11 31.18,60.81 31.18,58.42 33.21,56.39 33.21,55.8 33.1,55.69 32.51,55.69 32.2,55.37 32.2,54.68 32.49,54.38 33.86,54.38 33.97,54.26 33.97,54.04 33.86,53.93 32.49,53.93 32.2,53.63 32.2,52.94 32.49,52.64 35.11,52.64 37.53,50.23 52.64,50.23 56.07,46.8 65.66,46.8 67.25,48.39 68.7,48.39 68.81,48.27 68.81,47.29 69.11,46.99 69.6,46.99 69.9,47.29 69.9,48.27 70.01,48.39 70.29,48.39 72.01,46.67 107.83,46.67 113.16,52.01 116.34,52.01 117.33,53 126.12,53 126.17,52.95 126.18,52.95 126.33,52.81 v1(126.36,52.81)
MIPI_DSI_TX1_D3N: length 127
  TOP w0.124: J5.37 33.13,60.69 32.96,60.51 32.96,60.3 33.09,60.17 33.09,60.17 v1(33.19,60.07) ; J22.30 130.82,56.53 130.91,56.44 131.64,56.44 v1(131.81,56.61)
  ART03 w0.113: v1(33.19,60.07) 32.84,59.73 32.84,59.46 32.57,59.19 32.57,58.87 34.48,56.96 37.23,56.96 37.53,56.66 37.53,55.65 37.23,55.35 35.86,55.35 35.75,55.24 35.75,54.93 35.85,54.83 37.22,54.83 37.53,54.52 37.53,52.52 38.67,51.37 53.09,51.37 56.58,47.88 64.9,47.88 66.48,49.46 70.93,49.46 72.52,47.88 107.06,47.88 113.28,54.1 125.16,54.1 125.47,54.42 126.87,54.42 127.12,54.66 127.12,56.09 127.41,56.39 127.94,56.39 128.24,56.09 128.24,54.53 128.35,54.42 128.58,54.42 128.69,54.53 128.69,56.09 128.99,56.39 129.48,56.39 129.78,56.09 129.78,54.53 129.89,54.42 130.11,54.42 130.23,54.53 130.23,55.96 130.52,56.26 131.47,56.26 131.81,56.6 v1(131.81,56.61)
MIPI_DSI_TX1_D3P: length 127.1
  TOP w0.124: J5.35 32.63,60.17 v1(32.53,60.07) ; v1(131.81,55.94) 131.64,56.11 130.91,56.11 130.82,56.02 J22.29
  ART03 w0.113: v1(32.53,60.07) 32.53,59.59 32.26,59.32 32.26,58.73 34.35,56.64 37.1,56.64 37.21,56.53 37.21,55.78 37.1,55.66 35.73,55.66 35.43,55.37 35.43,54.8 35.72,54.51 37.09,54.51 37.21,54.39 37.21,52.38 38.54,51.05 52.96,51.05 56.45,47.56 65.03,47.56 66.61,49.15 70.8,49.15 72.39,47.56 107.19,47.56 113.41,53.79 125.29,53.79 125.6,54.1 127,54.1 127.43,54.53 127.43,55.96 127.54,56.07 127.81,56.07 127.93,55.96 127.93,54.4 128.22,54.1 128.71,54.1 129.01,54.4 129.01,55.96 129.12,56.07 129.35,56.07 129.46,55.96 129.46,54.4 129.76,54.1 130.24,54.1 130.54,54.4 130.54,55.83 130.66,55.94 v1(131.81,55.94)
OTG0_DM: length 10.7
  TOP w0.158: v1(27.06,84.83) 27.06,83.04 J19.A7 27.08,81.82 27.24,81.66 27.94,81.66 28.08,81.8 J19.B7
  BOTTOM w0.158: v1(27.06,84.83) 27.27,84.62 27.27,83.79 26.74,83.26 26.74,81.36 D30.2 26.42,81.02 R133.1
OTG0_DP: length 10.6
  TOP w0.158: J19.B6 26.58,84.63 26.57,84.63 26.57,85.04 26.86,85.32 27.33,85.32 27.72,84.93 v1(27.72,84.83) 27.58,84.69 J19.A6
  BOTTOM w0.158: v1(27.72,84.83) 27.64,84.75 27.64,83.64 27.1,83.11 27.1,81.36 D31.2 27.44,80.01 R134.1
PCIE20_CLKREQN_M0: length 80.3
  TOP w0.156: J7.37 58.13,60.61 v1(57.63,60.11)
  ART03 w0.142: v1(57.63,60.11) 57.15,59.63 57.15,58.55 58.17,57.53 62.61,57.53 63.5,56.64 64.9,56.64 67.56,53.97 84.84,53.97 86.23,55.37 90.81,55.37 91.14,55.71 102.95,55.71 105.66,58.42 v1(117.6,58.42)
  BOTTOM w0.156: R207.1 113.54,66.42 114.05,65.91 116.46,65.91 118.09,64.28 118.09,58.9 v1(117.6,58.42)
PCIE20_PERSTN_M0: length 48.3
  TOP w0.156: J7.59 v1(63.63,60.11)
  ART03 w0.142: v1(63.63,60.11) 64.39,59.35 64.39,59.05 64.83,58.61 66.36,58.61 68.64,56.32 76.64,56.32 77.72,57.4 80.9,57.4 81.41,56.89 84.2,56.89 85.43,58.12 95.33,58.12 96.01,58.8 102.62,58.8 104.65,60.83 v1(104.65,61.59)
  BOTTOM w0.156: R209.2 v1(104.65,61.59)
PCIE20_REFCLKN: length 112.3
  TOP w0.179: J27.11 112,70.1 111.79,69.9 111.79,68.45 109.22,65.88 109.22,61.34 110.9,59.66 110.9,47.52 107.7,44.32 77.22,44.32 69.47,36.57 43.24,36.57 37.07,30.41 37.07,25.96 37.13,25.9 J4.54
PCIE20_REFCLKP: length 112.3
  TOP w0.179: J4.52 36.63,25.9 36.69,25.96 36.69,30.57 43.08,36.96 69.31,36.96 77.06,44.7 107.54,44.7 110.51,47.68 110.51,59.51 108.84,61.18 108.84,66.04 111.41,68.61 111.41,69.9 111.2,70.1 J27.13
PCIE20_RXN: length 115.2
  TOP w0.179: J4.48 35.63,25.9 35.57,25.96 35.57,27.36 arc(35.62,27.49) 35.76,27.54 arc(35.89,27.6) 35.94,27.73 35.94,28.07 arc(35.89,28.2) 35.76,28.26 arc(35.62,28.31) 35.57,28.44 35.57,32.34 40.82,37.59 68.87,37.59 76.74,45.46 106.46,45.46 109.47,48.48 109.47,59.43 108.08,60.83 108.08,67.36 106.3,69.14 104.25,69.14 103.79,69.59 103.79,69.9 104,70.1 J27.23
PCIE20_RXP: length 114.8
  TOP w0.179: J4.46 35.13,25.9 35.19,25.96 35.19,32.5 40.66,37.97 68.71,37.97 76.58,45.85 106.3,45.85 109.09,48.64 109.09,59.28 107.7,60.67 107.7,67.2 106.14,68.76 104.09,68.76 103.41,69.44 103.41,69.9 103.2,70.1 J27.25
PCIE20_TXN: length 98.4
  TOP w0.179: J4.44 34.63,25.9 34.57,25.96 34.57,34.62 38.56,38.61 68.47,38.61 76.34,46.48 105.95,46.48 107.82,48.35 107.82,57.41 C165.1
PCIE20_TXP: length 98.4
  TOP w0.179: C166.1 107.44,57.28 107.44,48.51 105.79,46.86 76.19,46.86 68.31,38.99 38.4,38.99 34.19,34.78 34.19,25.96 34.13,25.9 J4.42
PCIE20_WAKEN_M0: length 78.9
  TOP w0.156: v1(57.63,59.09) 58.63,60.09 J7.39
  ART03 w0.142: v1(117.6,59.43) 105.79,59.43 103,56.64 91.19,56.64 90.42,55.88 85.98,55.88 84.58,54.48 67.82,54.48 65.15,57.15 64.01,57.15 63.12,58.04 58.55,58.04 58.24,58.35
  ART03 w0.156: 58.24,58.35 57.63,58.95 v1(57.63,59.09)
  BOTTOM w0.156: v1(117.6,59.43) 117.6,64.01 116.33,65.28 113.41,65.28 112.52,66.17 R206.1
PCIE_PWR_EN: length 99.9
  TOP w0.156: J4.43 v1(34.63,22.1)
  ART03 w0.142: v1(34.63,22.1) 39.12,22.1 41.02,20.19 49.02,20.19 51.18,22.35 51.18,30.86 54.23,33.91 58.17,33.91 60.96,36.7 86.61,36.7 87.15,37.23 v1(95.63,37.23)
  BOTTOM w0.156: v1(95.63,37.23) 107.59,37.23 108.09,37.73 R204.1
PE_TXN: length 17.8
  TOP w0.179: J27.31 100.8,70.1 100.59,69.9 100.59,69.41 102.06,67.94 105.54,67.94 107.06,66.42 107.06,60.2 107.7,59.56 107.7,59.05 C165.2
PE_TXP: length 17.8
  TOP w0.179: J27.33 100,70.1 100.21,69.9 100.21,69.25 101.9,67.56 105.38,67.56 106.68,66.26 106.68,60.04 107.31,59.4 107.31,58.92 C166.2
PHY1_LED1: length 40.1
  TOP w0.203: v1(87.63,61.47) 86,61.47 U16.33
  BOTTOM w0.254: J17.14 73.18,81.95 73.18,77.18 73.91,76.45 80.64,76.45 83.06,74.04 83.06,66.82 87.63,62.24 v1(87.63,61.47) 87.12,60.96 R116.1
PHY1_LED2: length 34.2
  TOP w0.203: v1(89.66,61.47) 89.03,62.1 86.07,62.1 U16.34
  BOTTOM w0.254: R117.1 90.17,60.96 v1(89.66,61.47) 86.49,64.64 86.49,73.91 85.09,75.31 85.09,83.29 J17.11
PHY_CLKOUT125: length 12.7
  TOP w0.156: R112.2 94.11,59.43 90.81,62.74 86.13,62.74 U16.35
PWM2_M0: length 18.3
  TOP w0.156: v1(19.68,64.64) 19.94,64.9 R17.1 ; v1(23.11,56.24) 23.11,54.99 23.37,54.74 24.51,54.74 25.63,55.85 J5.8
  BOTTOM w0.156: v1(23.11,56.24) 22.48,56.87 22.48,64.13 21.97,64.64 v1(19.68,64.64)
PWM3_IR: length 169.5
  TOP w0.156: J5.7 25.63,60.48 25.47,60.32 23.75,60.32 21.21,57.78 21.21,43.18 20.19,42.16 20.19,28.32 19.68,27.81 14.48,27.81 12.7,26.03 12.7,24.64 13.34,24 13.34,20.06 v1(13.84,19.56)
  ART03 w0.142: v1(124.84,13.46) 124.21,14.1 122.56,14.1 120.84,12.38 72.45,12.38 69.85,14.98 55.49,14.98 54.48,13.97 36.45,13.97 32.19,18.22 28.26,18.22 28.07,18.41 25.27,18.41 24.13,19.56 v1(13.84,19.56)
  BOTTOM w0.156: R46.1 C62.1 v1(124.84,13.46)
PWR_3V3_EN: length 61.9
  TOP w0.156: J6.59 63.63,19.33 63.47,19.18 v1(63.11,19.18)
  ART03 w0.142: v1(63.11,19.18) 62.61,19.68 50.67,19.68 49.66,18.67 39.62,18.67 37.34,20.95 30.1,20.95 29.59,21.46 29.59,25.02 29.08,25.53 29.08,27.56 27.97,28.68 18.82,28.68 v1(15.37,32.13)
  BOTTOM w0.156: v1(15.37,32.13) 15.37,31.11 15.1,30.85 R30.1
PWR_5V_EN: length 28.8
  TOP w0.156: J4.35 32.63,21.85 32.38,22.1 v1(31.63,22.1)
  ART03 w0.142: v1(14.48,35.42) 15.55,35.42 20.4,30.58 28.27,30.58 31.11,27.74 31.11,22.61 v1(31.63,22.1)
  BOTTOM w0.156: R32.1 v1(14.48,35.42)
PWR_12V_EN: length 31.4
  TOP w0.156: v1(33.13,23.11) 34.13,22.11 J4.41
  ART03 w0.142: v1(16.76,39.07) 16.76,34.93 20.65,31.04 29.29,31.04 32.64,27.68 32.64,23.6 v1(33.13,23.11)
  BOTTOM w0.156: R28.1 v1(16.76,39.07)
PWRON_KEY: length 88.9
  TOP w0.156: J4.25 30.13,19.08 29.34,18.29 24.51,18.29 v1(23.88,18.92) ; v1(3.67,73.4) C56.1 D3.2 3.67,75.57 4.28,76.18 SW1.3 SW1.4
  ART03 w0.142: v1(23.88,18.92) 23.37,18.41 13.34,18.41 12.7,19.05 12.7,28.45 10.92,30.22 6.49,30.22 5.46,31.26 5.46,46.35 2.79,49.02 2.79,61.97 3.67,62.86 v1(3.67,73.4)
RECOVERY: length 81.7
  TOP w0.156: J6.16 52.63,26.87 50.8,28.7 47.12,28.7 45.09,26.67 45.09,23.24 v1(45.59,22.73) ; R41.2 5.47,56.89 6.6,55.75 v1(10.54,55.75)
  ART03 w0.142: v1(10.54,55.75) 10.54,54.35 16.64,48.26 16.64,42.44 17.18,41.9 17.18,40.22 18.03,39.37 18.03,35.18 20.7,32.51 36.29,32.51 36.62,32.18 36.62,26.12 38.73,24 44.32,24 v1(45.59,22.73)
RESET_KEY: length 79.5
  TOP w0.156: SW2.4 SW2.3 4.28,67.16 3.67,66.55 D4.2 C58.1 3.67,64 3.43,63.75 v1(3.43,61.34) ; J4.29 31.13,19.44 29.46,17.78 24,17.78 v1(22.86,18.92)
  ART03 w0.142: v1(22.86,18.92) 13.72,18.92 13.21,19.43 13.21,28.83 11.3,30.73 7.13,30.73 6.6,31.26 6.6,45.97 3.43,49.15 v1(3.43,61.34)
RS485_1_A: length 62.1
  TOP w0.254: v1(49.02,10.23) 49.56,9.7 51.41,9.7 53.17,11.46 58.46,11.46 59.47,12.48 65.07,12.48 66.55,13.95 66.55,15.62 66.93,16 J13.1
  BOTTOM w0.254: U14.6 R71.2 52.48,35.7 52.48,30.95 D26.2 52.73,29.07 52.48,28.81 52.48,27.33 50.57,25.42 50.57,21.02 51,20.6 52.89,20.6 53.83,19.66 53.83,11.14 52.38,9.7 49.56,9.7 v1(49.02,10.23) R80.1
RS485_1_B: length 55
  TOP w0.254: R73.1 66.14,14.85 66.14,14.12 64.9,12.88 59.3,12.88 58.29,11.87 53,11.87 51.37,10.23 v1(50.55,10.23)
  BOTTOM w0.254: R79.1 v1(50.55,10.23) 52.34,10.23 53.42,11.31 53.42,19.5 52.72,20.19 50.83,20.19 50.16,20.85 50.16,25.59 52.07,27.5 52.07,28.81 51.82,29.07 D24.2 52.07,30.97 52.07,35.55 R76.1 51.57,36.08 U14.7
RS485_2_A: length 59.9
  TOP w0.254: J14.1 59.18,14.52 58.46,13.8 43.56,13.8 41.96,12.2 41.96,10.78 v1(41.4,10.23)
  BOTTOM w0.254: U15.6 R72.2 44.07,35.68 44.07,30.97 D27.2 44.32,29.07 44.07,28.81 44.07,22.49 41.99,20.42 39.58,20.42 38.1,18.94 38.1,11.3 39.62,9.78 41.15,9.78 41.4,10.03 v1(41.4,10.23) R82.1
RS485_2_B: length 65.4
  TOP w0.254: v1(42.93,10.23) 42.36,10.79 42.36,12.03 43.73,13.4 58.63,13.4 59.83,14.6 63.41,14.6 63.43,14.62 63.56,14.62 R74.1
  BOTTOM w0.254: U15.7 43.17,37.76 R78.1 43.56,35.68 43.56,30.85 D25.2 43.41,29.07 43.66,28.81 43.66,22.66 41.83,20.83 39.41,20.83 37.69,19.11 37.69,11.13 39.46,9.37 41.32,9.37 42.17,10.23 v1(42.93,10.23) R81.1
RX8010_NIRQ1: length 47.7
  TOP w0.156: J5.64 39.63,52.33 38.23,50.93 23.5,50.93 v1(22.99,50.42)
  BOTTOM w0.156: U12.7 16.76,69.59 17.78,68.58 17.78,64.26 18.54,63.5 20.95,63.5 21.46,62.99 21.46,51.94 v1(22.99,50.42)
RX8010_NIRQ2: length 43.1
  TOP w0.156: v1(22.99,51.43) 37.97,51.43 39.13,52.59 J5.62
  BOTTOM w0.156: U12.3 19.97,68.32 19.05,67.41 19.05,64.39 19.3,64.13 21.59,64.13 21.97,63.75 21.97,52.45 v1(22.99,51.43)
RXD1_232: length 12
  BOTTOM w0.254: D12.2 27.43,27.22 R58.1
  BOTTOM w0.305: U13.13 29.08,35.69 29.46,35.3 29.46,31.1 D12.2
RXD2_232: length 25.9
  BOTTOM w0.254: R56.1 36.07,28.94 D11.2 37.96,29.07 39.12,30.22 39.12,43.69 38.23,44.58 34.54,44.58 34.16,44.19 U13.8
SARADC_VIN1: length 82
  TOP w0.156: v1(13.34,37.84) 12.7,37.21 9.65,37.21 8.26,38.61 8.26,45.31 6.57,46.99 R43.2 ; v1(45.59,19.18) 45.34,19.43 45.34,22.1 44.58,22.86 44.58,27.1 46.74,29.26 51.16,29.26 53.13,27.29 J6.18
  ART03 w0.142: v1(13.34,37.84) 13.46,37.72 13.46,34.8 14.54,33.72 15.74,33.72 20.24,29.21 28.19,29.21 29.59,27.81 29.59,25.65 30.1,25.14 30.1,21.84 30.48,21.46 37.97,21.46 40.26,19.18 v1(45.59,19.18)
SDMMC0_CLK: length 77.7
  TOP w0.156: v1(52.63,23.12) 52.13,22.62 J6.13
  ART03 w0.142: v1(114.55,29.08) 115.57,30.1 115.57,32.26 114.15,33.68 98.45,33.68 96.65,31.88 69.6,31.88 67.84,30.12 54.92,30.12 52.63,27.83 v1(52.63,23.12)
  BOTTOM w0.156: R63.1 v1(114.55,29.08)
SDMMC0_CMD: length 78.2
  TOP w0.156: J6.15 v1(52.63,22.1)
  ART03 w0.142: v1(114.55,26.29) 113.79,27.05 113.79,30.99 112.81,31.97 100.42,31.97 97.66,29.21 93.79,29.21 93.65,29.07 93.65,28.59 93.51,28.45 93.22,28.45 93.08,28.59 93.08,29.07 92.94,29.21 88.9,29.21 88.07,30.04 70.18,30.04 68.55,28.41 55.88,28.41 55.12,27.65 55.12,22.93 54.77,22.58 54.43,22.58 54.11,22.26 54.11,21.91 53.83,21.63 53.11,21.63 v1(52.63,22.1)
  BOTTOM w0.156: R62.1 v1(114.55,26.29)
SDMMC0_D0: length 77.1
  TOP w0.156: J6.19 v1(53.63,22.1)
  ART03 w0.142: v1(53.63,22.1) 53.63,22.45 54.15,22.97 54.15,27.89 55.53,29.27 68.2,29.27 69.92,30.99 89.27,30.99 89.41,30.84 89.41,30.35 89.56,30.2 89.84,30.2 89.98,30.35 89.98,30.84 90.13,30.99 90.41,30.99 90.55,30.84 90.55,30.35 90.7,30.2 90.98,30.2 91.12,30.35 91.12,30.84 91.27,30.99 91.55,30.99 91.69,30.84 91.69,30.35 91.84,30.2 92.12,30.2 92.26,30.35 92.26,30.84 92.41,30.99 97.16,30.99 98.99,32.82 113.48,32.82 114.3,32 114.81,32 115.03,31.78 115.03,30.7 v1(114.55,30.22)
  BOTTOM w0.156: R64.1 v1(114.55,30.22)
SDMMC0_D1: length 77.2
  TOP w0.156: v1(54.63,23.12) 54.13,22.62 J6.21
  ART03 w0.142: v1(54.63,23.12) 54.61,23.14 54.61,27.75 55.7,28.84 68.37,28.84 70,30.47 88.4,30.47 89.15,29.72 92.73,29.72 92.87,29.86 92.87,30.42 93.02,30.56 93.3,30.56 93.44,30.42 93.44,29.86 93.59,29.72 93.87,29.72 94.01,29.86 94.01,30.42 94.16,30.56 94.44,30.56 94.58,30.42 94.58,29.86 94.73,29.72 95.01,29.72 95.15,29.86 95.15,30.42 95.3,30.56 95.58,30.56 95.72,30.42 95.72,29.86 95.87,29.72 96.15,29.72 96.29,29.86 96.29,30.42 96.44,30.56 96.72,30.56 96.86,30.42 96.86,29.86 97.01,29.72 97.29,29.72 97.75,30.18 97.75,30.38 97.57,30.56 97.57,30.77 97.77,30.97 97.97,30.97 98.16,30.78 98.36,30.78 99.97,32.4 113.14,32.4 114.17,31.37 v1(114.55,31.37)
  BOTTOM w0.156: R65.1 v1(114.55,31.37)
SDMMC0_D2: length 75.7
  TOP w0.156: J6.23 v1(54.63,22.1)
  ART03 w0.142: v1(114.55,24) 112.78,25.78 112.78,29.97 111.63,31.11 100.89,31.11 97.97,28.19 97.41,28.19 96.6,27.38 89.08,27.38 87.27,29.18 70.53,29.18 68.91,27.56 57.28,27.56 56.64,26.92 56.64,25.4 56.15,24.91 56.15,22.02 55.81,21.68 55.06,21.68 v1(54.63,22.1)
  BOTTOM w0.156: R60.1 v1(114.55,24)
SDMMC0_D3: length 77.8
  TOP w0.156: J6.25 55.13,22.62 v1(55.63,23.12)
  ART03 w0.142: v1(55.63,23.12) 55.63,23.12 55.63,27.48 56.13,27.99 68.73,27.99 70.35,29.61 87.74,29.61 89.41,27.94 90,27.94 90.15,28.08 90.15,28.64 90.29,28.78 90.57,28.78 90.72,28.64 90.72,28.08 90.86,27.94 91.14,27.94 91.29,28.08 91.29,28.64 91.43,28.78 91.71,28.78 91.86,28.64 91.86,28.08 92,27.94 95.63,27.94 96.39,28.7 97.87,28.7 100.71,31.54 112.6,31.54 113.28,30.86 113.28,26.41 v1(114.55,25.14)
  BOTTOM w0.156: R61.1 v1(114.55,25.14)
SDMMC0_DET: length 72.3
  TOP w0.156: J6.17 53.13,22.62 v1(53.63,23.12)
  ART03 w0.142: v1(53.63,23.12) 53.09,23.66 53.09,27.68 55.1,29.7 68.02,29.7 69.74,31.41 96.82,31.41 98.66,33.25 113.81,33.25 v1(114.55,32.51)
  BOTTOM w0.156: R66.1 v1(114.55,32.51)
SIM_CLK0: length 22.5
  TOP w0.156: J27.12 111.6,60.99 112.3,60.29 112.3,44.89 v1(113.63,43.56)
  BOTTOM w0.156: R200.1 114.64,44.58 v1(113.63,43.56)
SIM_DATA0: length 23.6
  TOP w0.156: v1(113.63,42.54) 114.11,43.03 114.11,43.87 112.78,45.21 112.78,60.58 112.4,60.95 J27.10
  BOTTOM w0.156: R202.1 114.64,41.53 v1(113.63,42.54)
SIM_RST0: length 26.9
  TOP w0.156: J27.14 110.8,61.09 111.83,60.07 111.83,43.49 113.63,41.69 v1(113.63,39.5)
  BOTTOM w0.156: v1(113.63,39.5) 114.64,38.48 R199.1
SIM_VDD: length 34.1
  TOP w0.381: J27.8 113.2,61.17 113.41,60.96 113.41,46 115.44,43.97 115.44,42.16 114.64,41.36 v1(114.64,40.51)
  ART03 w0.635: v1(119.12,40.13) 117.92,41.32 115.46,41.32 v1(114.64,40.51)
  BOTTOM w0.381: U36.1 121.41,40.26 120.82,40.85 U37.1 v1(119.12,40.13) ; R198.1 v1(114.64,40.51)
SPKN_OUT: length 55.3
  TOP w0.254: v1(28.96,48.51) 29.54,47.93 29.54,25.96 29.63,25.87 J4.24
  BOTTOM w0.254: J31.2 30.89,75.29 30.89,72.36 D46.2 31.01,70.76 31.01,66.43 28.63,64.04 28.63,63.29 26.45,61.11 26.45,56.13 28.8,53.77 28.8,48.67 v1(28.96,48.51)
SPKP_OUT: length 55.5
  TOP w0.254: J4.22 29.13,47.45 v1(28.07,48.51)
  BOTTOM w0.254: J31.1 30.48,74.72 30.48,72 D45.2 30.61,70.86 30.61,66.6 28.22,64.21 28.22,63.46 26.04,61.28 26.04,55.96 28.4,53.61 28.4,48.84 v1(28.07,48.51)
SS_TXN: length 11.7
  BOTTOM w0.158: C112.1 96.52,68.82 96.52,69.38 96.33,69.57 96.33,70 96.26,70.07 U19.2 U19.9 96.33,71.46 96.33,74.01 96.49,74.17 96.49,75.98 95.99,76.48 95.99,77.64 96.45,78.1 96.45,78.71 96.29,78.87 J18.8
SS_TXP: length 11.8
  BOTTOM w0.158: J18.9 97.03,78.87 96.81,78.65 96.81,77.95 96.35,77.49 96.35,76.63 96.85,76.13 96.85,74.02 96.69,73.86 96.69,71.46 U19.10 U19.1 96.76,70.07 96.69,70 96.69,69.72 96.88,69.53 96.88,68.97 C113.1
TXD1_232: length 13.8
  BOTTOM w0.305: R59.1 23.24,26.96 D14.2 25.4,31.23 25.4,35.43 25.91,35.94 27.43,35.94 27.82,36.33 U13.14
TXD2_232: length 27.1
  BOTTOM w0.254: R57.1 D13.2 34.13,31.19 37.67,31.19 38.35,31.88 38.35,41.65 37.97,42.04 35.43,42.04 34.67,41.27 33.27,41.27 32.9,41.65 U13.7
UART1_DIR: length 31.5
  TOP w0.156: J7.43 v1(59.63,60.11)
  BOTTOM w0.156: v1(59.63,60.11) 58.91,60.83 52.42,60.83 52.11,60.52 52.11,59.1 50.67,57.66 50.67,54.99 51.18,54.48 51.18,46.23 51.7,45.71 R75.1 51.7,44.58 51.56,44.44 51.56,42.79 U14.2 51.57,41.9 51.82,41.65 52.58,41.65 52.84,41.92 U14.3
UART1_RX_M0: length 17.7
  TOP w0.156: v1(50.65,54.23) 51.13,54.71 J7.10
  BOTTOM w0.156: v1(50.65,54.23) 50.65,44.43 50.3,44.08 U14.1 50.3,42.04 50.04,41.78 49.53,41.78 49.28,42.03 R69.2
UART1_TX_M0: length 19.1
  TOP w0.156: J7.8 50.63,55.24 50.16,54.78 50.16,49.07 54.1,45.13 v1(54.1,44.45)
  BOTTOM w0.156: v1(54.1,44.45) 54.11,44.44 U14.4 54.11,42.15 54.48,41.78 54.86,41.78 55.11,42.03 R67.2
UART2_RX_M0_DEBUG: length 53.1
  TOP w0.156: J5.22 29.13,53.97 27.22,52.07 22.51,52.07 22.35,51.91 22.35,42.42 21.84,41.91 21.84,27.51 20.91,26.58 15.07,26.58 v1(13.89,25.4)
  BOTTOM w0.156: U10.4 9.64,27.67 10.03,28.07 13.46,28.07 13.89,27.64 v1(13.89,25.4) 13.84,25.4 13.84,25.41 R42.2
UART2_TX_M0_DEBUG: length 55
  TOP w0.156: J5.20 28.63,54.18 27.02,52.57 22.27,52.57 21.85,52.15 21.85,42.81 21.29,42.25 21.29,27.85 20.66,27.22 14.82,27.22 13.34,25.74 13.34,24.89 13.89,24.34 v1(13.89,21.34)
  BOTTOM w0.156: v1(13.89,21.34) R38.2 13.21,20.32 12.57,19.68 10.67,19.68 10.29,20.06 U9.2
UART3_RX_M1: length 41.3
  TOP w0.156: v1(35.69,37.97) 34.16,39.5 34.16,43.85 37.59,47.28 42.96,47.28 46.99,51.31 46.99,61.09 49.1,63.2 49.7,63.2 50.13,62.77 J7.5
  BOTTOM w0.156: U13.9 34.16,38.58 34.31,38.73 34.92,38.73 v1(35.69,37.97) R52.2
UART3_TX_M1: length 38.6
  TOP w0.156: v1(35.69,38.99) 34.67,40 34.67,43.56 37.96,46.85 43.42,46.85 47.37,50.8 47.37,59.69 47.88,60.2 49.16,60.2 49.63,60.67 J7.3
  BOTTOM w0.156: R53.2 v1(35.69,38.99) 35.31,39.37 33.27,39.37 32.9,38.99 U13.10
UART4_RX_M1: length 39.7
  TOP w0.156: J7.9 51.13,59.89 50.67,59.43 48.64,59.43 48.13,58.93 48.13,50.04 43.94,45.85 38.73,45.85 35.69,42.8 v1(35.69,41.02)
  BOTTOM w0.156: U13.12 30.36,39.04 31.72,40.41 35.08,40.41 v1(35.69,41.02) R54.2
UART4_TX_M1: length 39.2
  TOP w0.156: J7.7 50.63,60.1 50.35,59.82 48.39,59.82 47.75,59.18 47.75,50.42 43.68,46.35 38.35,46.35 35.18,43.18 35.18,40.51 v1(35.69,40)
  BOTTOM w0.156: U13.11 31.62,38.81 32.82,40 v1(35.69,40) R55.2
UART6_DIR: length 41.3
  TOP w0.156: v1(59.63,59.09) 60.13,59.59 J7.45
  BOTTOM w0.156: v1(59.63,59.09) 60.11,59.58 60.11,60.41 59.18,61.34 51.97,61.34 51.05,60.42 51.05,59.69 49.61,58.25 49.61,46.82 48.64,45.85 43.6,45.85 43.44,45.69 R77.1 43.44,44.58 43.18,44.32 43.18,42.79 U15.2 43.19,41.77 43.31,41.65 44.3,41.65 44.46,41.81 U15.3
UART6_RX_M0: length 28.2
  TOP w0.156: J7.13 52.13,59.59 51.59,59.05 48.89,59.05 48.64,58.8 48.64,49.78 43.94,45.08 v1(41.91,45.08)
  BOTTOM w0.156: R70.2 40.9,42.03 41.15,41.78 41.52,41.78 41.92,42.18 U15.1 41.92,45.08 v1(41.91,45.08)
UART6_TX_M0: length 26
  TOP w0.156: J7.11 v1(51.63,60.11)
  BOTTOM w0.156: R68.2 46.73,42.03 46.35,41.65 45.97,41.65 45.73,41.9 U15.4 45.72,42.79 45.72,44.07 45.97,44.32 49.4,44.32 50.16,45.08 50.16,57.91 51.63,59.38 v1(51.63,60.11)
UART7_RX_M0: length 80.5
  TOP w0.156: J7.17 53.13,59.59 v1(52.63,59.09) ; R223.2 v1(100.33,22.35)
  ART03 w0.142: v1(100.33,22.35) 99.06,23.62 79.76,23.62 78.14,22 78.14,21.05 v1(78.61,20.57)
  BOTTOM w0.156: v1(52.63,59.09) 52.63,58.73 51.15,57.24 51.15,55.28 51.69,54.74 51.69,47.75 59.31,40.13 61.34,40.13 77.98,23.49 77.98,21.21 v1(78.61,20.57)
UART7_TX_M0: length 75.3
  TOP w0.156: J7.15 v1(52.63,60.11) ; R224.2 v1(99.31,22.35)
  ART03 w0.142: v1(99.31,22.35) 98.55,23.11 80.14,23.11 v1(78.61,21.59)
  BOTTOM w0.156: v1(52.63,60.11) 53.11,59.63 53.11,58.57 52.2,57.66 52.2,48 59.56,40.64 61.47,40.64 78.61,23.49 v1(78.61,21.59)
